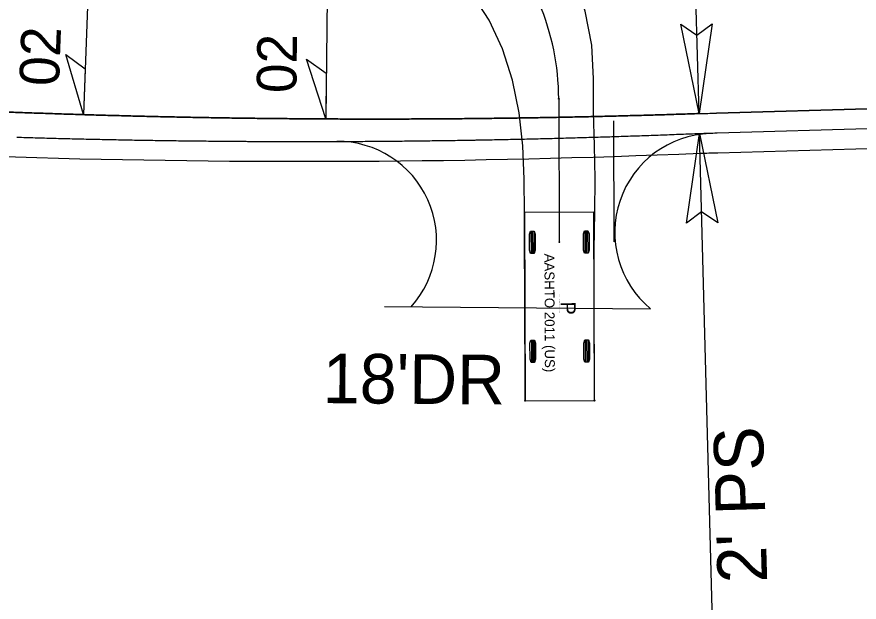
# Model space of a CAD drawing. Extents: x 1755545 to 1761252, y 736169 to 737766.
# Drawn here: x 1757215.5 to 1757300.5, y 736904.9 to 736964 of the extents above; entities that cross this region are included whole.
import ezdxf

# ---------------------------------------------------------------- set-up
doc = ezdxf.new("R2010")
doc.units = 0
for name, color, linetype in [('Exist Contamination Potential Cell', 7, 'Continuous'), ('Exist Cultural Church Label', 7, 'Continuous'), ('Old_Level_1', 7, 'Continuous'), ('Prop Dimension', 7, 'Continuous'), ('Prop Paved Shoulder', 7, 'Continuous'), ('Prop Shade Light', 7, 'Continuous'), ('Prop Superelevation Label', 7, 'Continuous'), ('Prop Terminator CELL', 7, 'Continuous'), ('Scratch_Level_2', 7, 'Continuous'), ('Scratch_Level_3', 7, 'Continuous'), ('Scratch_Level_4', 7, 'Continuous'), ('Scratch_Level_6', 7, 'Continuous')]:
    doc.layers.add(name, color=color, linetype=linetype)

msp = doc.modelspace()

# ---------------------------------------------------------------- linework, layer by layer
at = {"layer": 'Exist Contamination Potential Cell'}
msp.add_line((1757286.12, 736954.256), (1757374.712, 736956.772), dxfattribs=at)
msp.add_arc((1757258.672, 737920.867), 967, 271.521596, 271.626536, dxfattribs=at)
for points in [[(1757147.07, 736959.322), (1757147.994, 736959.222), (1757148.918, 736959.123), (1757149.843, 736959.024), (1757150.767, 736958.927), (1757151.691, 736958.831), (1757152.616, 736958.735), (1757153.54, 736958.64), (1757154.465, 736958.547), (1757155.39, 736958.454), (1757156.315, 736958.362), (1757157.24, 736958.271), (1757158.165, 736958.18), (1757159.09, 736958.091), (1757160.015, 736958.003), (1757160.94, 736957.915), (1757161.866, 736957.828), (1757162.791, 736957.743), (1757163.716, 736957.658), (1757164.642, 736957.574), (1757165.568, 736957.491), (1757166.493, 736957.408), (1757167.419, 736957.327), (1757168.345, 736957.247), (1757169.271, 736957.167), (1757170.197, 736957.088), (1757171.123, 736957.011), (1757172.049, 736956.934), (1757172.975, 736956.858), (1757173.901, 736956.783), (1757174.828, 736956.708), (1757175.754, 736956.635), (1757176.68, 736956.563), (1757177.607, 736956.491), (1757178.533, 736956.42), (1757179.46, 736956.351), (1757180.387, 736956.282), (1757181.314, 736956.214), (1757182.24, 736956.147), (1757183.167, 736956.08), (1757184.094, 736956.015), (1757185.021, 736955.951), (1757185.948, 736955.887), (1757186.875, 736955.824), (1757187.802, 736955.763), (1757188.73, 736955.702), (1757189.657, 736955.642), (1757190.584, 736955.583), (1757191.511, 736955.525), (1757192.439, 736955.467), (1757193.366, 736955.411), (1757194.294, 736955.355), (1757195.221, 736955.301), (1757196.149, 736955.247), (1757197.076, 736955.194), (1757198.004, 736955.142), (1757198.932, 736955.091), (1757199.86, 736955.041), (1757200.787, 736954.992), (1757201.715, 736954.943), (1757202.643, 736954.896), (1757203.571, 736954.849), (1757204.499, 736954.804), (1757205.427, 736954.759), (1757206.355, 736954.715), (1757207.283, 736954.672), (1757208.211, 736954.63), (1757209.139, 736954.588), (1757210.067, 736954.548), (1757210.995, 736954.508), (1757211.924, 736954.47), (1757212.852, 736954.432), (1757213.78, 736954.395), (1757214.708, 736954.359), (1757215.637, 736954.324)], [(1757215.637, 736954.324), (1757216.565, 736954.29), (1757217.494, 736954.257), (1757218.422, 736954.225), (1757219.35, 736954.193), (1757220.279, 736954.163), (1757221.207, 736954.133), (1757222.136, 736954.104), (1757223.064, 736954.076), (1757223.993, 736954.049), (1757224.921, 736954.023), (1757225.85, 736953.998), (1757226.779, 736953.974), (1757227.707, 736953.95), (1757228.636, 736953.928), (1757229.565, 736953.906), (1757230.493, 736953.885), (1757231.422, 736953.866), (1757232.351, 736953.847), (1757233.279, 736953.829), (1757234.208, 736953.811), (1757235.137, 736953.795), (1757236.065, 736953.78), (1757236.994, 736953.765), (1757237.923, 736953.752), (1757238.852, 736953.739), (1757239.78, 736953.727), (1757240.709, 736953.716), (1757241.638, 736953.706), (1757242.567, 736953.697), (1757243.495, 736953.689), (1757244.424, 736953.681), (1757245.353, 736953.675), (1757246.282, 736953.669), (1757247.21, 736953.664), (1757248.139, 736953.661), (1757249.068, 736953.658), (1757249.997, 736953.656), (1757250.925, 736953.655), (1757251.854, 736953.654), (1757252.783, 736953.655), (1757253.712, 736953.657), (1757254.64, 736953.659), (1757255.569, 736953.662), (1757256.498, 736953.667), (1757257.426, 736953.672), (1757258.355, 736953.678), (1757259.284, 736953.685), (1757260.212, 736953.692), (1757261.141, 736953.701), (1757262.07, 736953.711), (1757262.998, 736953.721), (1757263.927, 736953.732), (1757264.855, 736953.745), (1757265.784, 736953.758), (1757266.713, 736953.772), (1757267.641, 736953.787), (1757268.57, 736953.803), (1757269.498, 736953.819), (1757270.426, 736953.837), (1757271.355, 736953.855), (1757272.283, 736953.875), (1757273.212, 736953.895), (1757274.14, 736953.916), (1757275.068, 736953.938), (1757275.997, 736953.961), (1757276.925, 736953.985), (1757277.853, 736954.01), (1757278.781, 736954.035), (1757279.709, 736954.062), (1757280.638, 736954.089), (1757281.566, 736954.118), (1757282.494, 736954.147), (1757284.35, 736954.208)]]:
    msp.add_spline(points, degree=3, dxfattribs=at)
at = {"layer": 'Exist Cultural Church Label'}
for points in [[(1757222.253, 736954.101), (1757220.48, 736960.172), (1757222.427, 736958.722)], [(1757246.688, 736953.667), (1757244.762, 736959.691), (1757246.745, 736958.292)]]:
    msp.add_lwpolyline(points, close=True, dxfattribs=at)
at = {"layer": 'Old_Level_1'}
msp.add_line((1757252.603, 736934.737), (1757279.451, 736934.524), dxfattribs=at)
for centre, start, end in [((1757285.844, 736942.213), 92.13259, 230.2561), ((1757247.867, 736941.408), 317.995, 90.37061)]:
    msp.add_arc(centre, 10, start, end, dxfattribs=at)
at = {"layer": 'Prop Dimension'}
for p, q in [((1757284.35, 736954.208), (1757283.898, 736971.202)), ((1757286.368, 736878.235), (1757284.403, 736952.207))]:
    msp.add_line(p, q, dxfattribs=at)
at = {"layer": 'Prop Paved Shoulder'}
msp.add_line((1757286.177, 736952.257), (1757374.768, 736954.773), dxfattribs=at)
msp.add_arc((1757258.672, 737920.867), 969, 271.521596, 271.626536, dxfattribs=at)
msp.add_spline([(1757215.526, 736951.827), (1757216.457, 736951.799), (1757217.388, 736951.773), (1757218.319, 736951.747), (1757219.25, 736951.722), (1757220.181, 736951.698), (1757221.112, 736951.675), (1757222.043, 736951.653), (1757222.974, 736951.632), (1757223.905, 736951.612), (1757224.837, 736951.592), (1757225.768, 736951.574), (1757226.699, 736951.556), (1757227.63, 736951.539), (1757228.561, 736951.524), (1757229.492, 736951.509), (1757230.424, 736951.495), (1757231.355, 736951.481), (1757232.286, 736951.469), (1757233.217, 736951.458), (1757234.148, 736951.447), (1757235.079, 736951.438), (1757236.01, 736951.429), (1757236.942, 736951.421), (1757237.873, 736951.414), (1757238.804, 736951.408), (1757239.735, 736951.403), (1757240.666, 736951.399), (1757241.597, 736951.396), (1757242.528, 736951.393), (1757243.459, 736951.392), (1757244.39, 736951.391), (1757245.321, 736951.391), (1757246.253, 736951.392), (1757247.184, 736951.394), (1757248.115, 736951.397), (1757249.046, 736951.401), (1757249.977, 736951.406), (1757250.907, 736951.411), (1757251.838, 736951.418), (1757252.769, 736951.425), (1757253.7, 736951.434), (1757254.631, 736951.443), (1757255.562, 736951.453), (1757256.493, 736951.464), (1757257.424, 736951.476), (1757258.354, 736951.489), (1757259.285, 736951.502), (1757260.216, 736951.517), (1757261.147, 736951.532), (1757262.077, 736951.549), (1757263.008, 736951.566), (1757263.939, 736951.584), (1757264.869, 736951.603), (1757265.8, 736951.623), (1757266.73, 736951.644), (1757267.661, 736951.665), (1757268.591, 736951.688), (1757269.522, 736951.711), (1757270.452, 736951.736), (1757271.382, 736951.761), (1757272.313, 736951.787), (1757273.243, 736951.814), (1757274.173, 736951.842), (1757275.103, 736951.871), (1757276.033, 736951.901), (1757276.964, 736951.931), (1757277.894, 736951.963), (1757278.824, 736951.995), (1757279.754, 736952.029), (1757280.684, 736952.063), (1757281.613, 736952.098), (1757282.543, 736952.134), (1757284.403, 736952.209)], degree=3, dxfattribs=at)
at = {"layer": 'Prop Shade Light'}
for p, q in [((1757374.712, 736956.772), (1757286.12, 736954.256)), ((1757286.177, 736952.257), (1757374.768, 736954.773))]:
    msp.add_line(p, q, dxfattribs=at)
for radius in [967, 969]:
    msp.add_arc((1757258.672, 737920.867), radius, 271.521596, 271.626536, dxfattribs=at)
for points in [[(1757215.637, 736954.324), (1757214.708, 736954.359), (1757213.78, 736954.395), (1757212.852, 736954.432), (1757211.924, 736954.47), (1757210.995, 736954.508), (1757210.067, 736954.548), (1757209.139, 736954.588), (1757208.211, 736954.63), (1757207.283, 736954.672), (1757206.355, 736954.715), (1757205.427, 736954.759), (1757204.499, 736954.804), (1757203.571, 736954.849), (1757202.643, 736954.896), (1757201.715, 736954.943), (1757200.787, 736954.992), (1757199.86, 736955.041), (1757198.932, 736955.091), (1757198.004, 736955.142), (1757197.076, 736955.194), (1757196.149, 736955.247), (1757195.221, 736955.301), (1757194.294, 736955.355), (1757193.366, 736955.411), (1757192.744, 736955.449)], [(1757238.538, 736953.743), (1757237.923, 736953.752), (1757236.994, 736953.765), (1757236.065, 736953.78), (1757235.137, 736953.795), (1757234.208, 736953.811), (1757233.279, 736953.829), (1757232.351, 736953.847), (1757231.422, 736953.866), (1757230.493, 736953.885), (1757229.565, 736953.906), (1757228.636, 736953.928), (1757227.707, 736953.95), (1757226.779, 736953.974), (1757225.85, 736953.998), (1757224.921, 736954.023), (1757223.993, 736954.049), (1757223.064, 736954.076), (1757222.136, 736954.104), (1757221.207, 736954.133), (1757220.279, 736954.163), (1757219.35, 736954.193), (1757218.422, 736954.225), (1757217.494, 736954.257), (1757216.565, 736954.29), (1757215.637, 736954.324)], [(1757261.447, 736953.704), (1757261.141, 736953.701), (1757260.212, 736953.692), (1757259.284, 736953.685), (1757258.355, 736953.678), (1757257.426, 736953.672), (1757256.498, 736953.667), (1757255.569, 736953.662), (1757254.64, 736953.659), (1757253.712, 736953.657), (1757252.783, 736953.655), (1757251.854, 736953.654), (1757250.925, 736953.655), (1757249.997, 736953.656), (1757249.068, 736953.658), (1757248.139, 736953.661), (1757247.21, 736953.664), (1757246.282, 736953.669), (1757245.353, 736953.675), (1757244.424, 736953.681), (1757243.495, 736953.689), (1757242.567, 736953.697), (1757241.638, 736953.706), (1757240.709, 736953.716), (1757239.78, 736953.727), (1757238.852, 736953.739), (1757238.538, 736953.743)], [(1757284.35, 736954.208), (1757282.494, 736954.147), (1757281.566, 736954.118), (1757280.638, 736954.089), (1757279.709, 736954.062), (1757278.781, 736954.035), (1757277.853, 736954.01), (1757276.925, 736953.985), (1757275.997, 736953.961), (1757275.068, 736953.938), (1757274.14, 736953.916), (1757273.212, 736953.895), (1757272.283, 736953.875), (1757271.355, 736953.855), (1757270.426, 736953.837), (1757269.498, 736953.819), (1757268.57, 736953.803), (1757267.641, 736953.787), (1757266.713, 736953.772), (1757265.784, 736953.758), (1757264.855, 736953.745), (1757263.927, 736953.732), (1757262.998, 736953.721), (1757262.07, 736953.711), (1757261.447, 736953.704)], [(1757261.449, 736951.537), (1757262.077, 736951.549), (1757263.008, 736951.566), (1757263.939, 736951.584), (1757264.869, 736951.603), (1757265.8, 736951.623), (1757266.73, 736951.644), (1757267.661, 736951.665), (1757268.591, 736951.688), (1757269.522, 736951.711), (1757270.452, 736951.736), (1757271.382, 736951.761), (1757272.313, 736951.787), (1757273.243, 736951.814), (1757274.173, 736951.842), (1757275.103, 736951.871), (1757276.033, 736951.901), (1757276.964, 736951.931), (1757277.894, 736951.963), (1757278.824, 736951.995), (1757279.754, 736952.029), (1757280.684, 736952.063), (1757281.613, 736952.098), (1757282.543, 736952.134), (1757284.403, 736952.209)], [(1757215.526, 736951.827), (1757216.457, 736951.799), (1757217.388, 736951.773), (1757218.319, 736951.747), (1757219.25, 736951.722), (1757220.181, 736951.698), (1757221.112, 736951.675), (1757222.043, 736951.653), (1757222.974, 736951.632), (1757223.905, 736951.612), (1757224.837, 736951.592), (1757225.768, 736951.574), (1757226.699, 736951.556), (1757227.63, 736951.539), (1757228.561, 736951.524), (1757229.492, 736951.509), (1757230.424, 736951.495), (1757231.355, 736951.481), (1757232.286, 736951.469), (1757233.217, 736951.458), (1757234.148, 736951.447), (1757235.079, 736951.438), (1757236.01, 736951.429), (1757236.942, 736951.421), (1757237.873, 736951.414), (1757238.486, 736951.41)], [(1757238.486, 736951.41), (1757238.804, 736951.408), (1757239.735, 736951.403), (1757240.666, 736951.399), (1757241.597, 736951.396), (1757242.528, 736951.393), (1757243.459, 736951.392), (1757244.39, 736951.391), (1757245.321, 736951.391), (1757246.253, 736951.392), (1757247.184, 736951.394), (1757248.115, 736951.397), (1757249.046, 736951.401), (1757249.977, 736951.406), (1757250.907, 736951.411), (1757251.838, 736951.418), (1757252.769, 736951.425), (1757253.7, 736951.434), (1757254.631, 736951.443), (1757255.562, 736951.453), (1757256.493, 736951.464), (1757257.424, 736951.476), (1757258.354, 736951.489), (1757259.285, 736951.502), (1757260.216, 736951.517), (1757261.147, 736951.532), (1757261.449, 736951.537)]]:
    msp.add_spline(points, degree=3, dxfattribs=at)
at = {"layer": 'Prop Superelevation Label'}
for p, q in [((1757223.465, 736986.271), (1757222.253, 736954.101)), ((1757247.095, 736986.568), (1757246.688, 736953.667))]:
    msp.add_line(p, q, dxfattribs=at)
at = {"layer": 'Prop Terminator CELL'}
for points in [[(1757285.66, 736963.246), (1757284.35, 736954.208), (1757282.51, 736963.212), (1757284.14, 736962.105)], [(1757283.092, 736943.169), (1757284.403, 736952.207), (1757286.243, 736943.203), (1757284.613, 736944.31)]]:
    msp.add_lwpolyline(points, close=True, dxfattribs=at)
at = {"layer": 'Scratch_Level_2'}
for p, q in [((1757270.198, 736955.7), (1757270.254, 736941.247)), ((1757275.707, 736953.469), (1757275.754, 736941.269)), ((1757273.742, 736944.261), (1757266.743, 736944.234)), ((1757266.743, 736944.234), (1757266.816, 736925.234)), ((1757266.743, 736944.234), (1757266.743, 736944.234)), ((1757273.816, 736925.261), (1757273.742, 736944.261)), ((1757267.39, 736942.361), (1757267.399, 736940.111)), ((1757267.531, 736942.362), (1757267.54, 736940.112)), ((1757267.672, 736942.362), (1757267.68, 736940.112)), ((1757272.828, 736942.382), (1757272.837, 736940.132)), ((1757272.969, 736942.383), (1757272.977, 736940.133)), ((1757273.109, 736942.383), (1757273.118, 736940.133)), ((1757267.433, 736931.361), (1757267.442, 736929.111)), ((1757267.574, 736931.362), (1757267.583, 736929.112)), ((1757267.714, 736931.362), (1757267.723, 736929.112)), ((1757272.871, 736931.382), (1757272.879, 736929.132)), ((1757273.011, 736931.383), (1757273.02, 736929.133)), ((1757273.152, 736931.383), (1757273.161, 736929.133)), ((1757266.816, 736925.234), (1757273.816, 736925.261))]:
    msp.add_line(p, q, dxfattribs=at)
for points in [[(1757273.816, 736925.261), (1757273.802, 736929.061), (1757273.787, 736932.861), (1757273.772, 736936.661), (1757273.761, 736940.461), (1757273.838, 736944.263), (1757273.838, 736944.263), (1757273.838, 736944.263), (1757273.873, 736947.632), (1757273.815, 736950.998), (1757273.703, 736954.344), (1757273.69, 736957.706), (1757273.539, 736961.091), (1757272.863, 736964.536), (1757271.664, 736967.948), (1757270.158, 736970.915)], [(1757266.816, 736925.234), (1757266.802, 736929.034), (1757266.787, 736932.834), (1757266.772, 736936.634), (1757266.757, 736940.434), (1757266.743, 736944.234), (1757266.743, 736944.234), (1757266.713, 736947.595), (1757266.57, 736950.952), (1757266.207, 736954.292), (1757265.541, 736957.583), (1757264.524, 736960.739), (1757263.179, 736963.618), (1757261.539, 736966.185), (1757259.841, 736968.215)]]:
    msp.add_lwpolyline(points, dxfattribs=at)
for points in [[(1757267.356, 736942.361), (1757267.707, 736942.362), (1757267.814, 736942.048), (1757267.82, 736940.428), (1757267.715, 736940.112), (1757267.364, 736940.111), (1757267.257, 736940.426), (1757267.251, 736942.046)], [(1757272.793, 736942.382), (1757273.144, 736942.383), (1757273.251, 736942.069), (1757273.257, 736940.449), (1757273.153, 736940.133), (1757272.802, 736940.132), (1757272.695, 736940.447), (1757272.689, 736942.067)], [(1757267.398, 736931.361), (1757267.749, 736931.362), (1757267.856, 736931.048), (1757267.863, 736929.428), (1757267.758, 736929.112), (1757267.407, 736929.111), (1757267.3, 736929.426), (1757267.294, 736931.046)], [(1757272.836, 736931.382), (1757273.187, 736931.384), (1757273.294, 736931.069), (1757273.3, 736929.449), (1757273.195, 736929.134), (1757272.844, 736929.132), (1757272.738, 736929.447), (1757272.731, 736931.067)]]:
    msp.add_lwpolyline(points, close=True, dxfattribs=at)
for centre in [(1757270.198, 736955.7), (1757270.254, 736941.247), (1757266.816, 736925.234), (1757273.816, 736925.261)]:
    msp.add_circle(centre, 0.0417, dxfattribs=at)
msp.add_arc((1757245.198, 736955.603), 25, 0.22255, 90.97942, dxfattribs=at)
at = {"layer": 'Scratch_Level_3'}
msp.add_arc((1757251.634, 737921.129), 967.474, 263.795377, 271.937839, dxfattribs=at)
at = {"layer": 'Scratch_Level_6'}
msp.add_line((1757286.234, 736950.258), (1757374.825, 736952.774), dxfattribs=at)
for centre, radius, start, end in [((1757244.599, 737921.442), 972.05, 264.207509, 272.349971), ((1757258.672, 737920.867), 971, 271.521596, 271.626536)]:
    msp.add_arc(centre, radius, start, end, dxfattribs=at)

# ---------------------------------------------------------------- texts
at = {"layer": 'Prop Dimension'}
msp.add_text("2' PS", height=5, rotation=91.62654, dxfattribs=at).set_placement((1757291.235, 736906.934))
at = {"layer": 'Prop Superelevation Label'}
for rotation, p in [(87.8426, (1757219.767, 736956.935)), (89.29008, (1757243.723, 736956.258))]:
    msp.add_text('02', height=4, rotation=rotation, dxfattribs=at).set_placement(p)
at = {"layer": 'Scratch_Level_2'}
for s, height, p in [('AASHTO 2011 (US)', 1, (1757268.754, 736940.081)), ('(c) 2014 Transoft Solutions, Inc. All rights reserved.', 0.06, (1757270.245, 736935.97)), ('P', 1.5, (1757270.397, 736935.248))]:
    msp.add_text(s, height=height, rotation=270.22255, dxfattribs=at).set_placement(p)
at = {"layer": 'Scratch_Level_4'}
msp.add_text("18'DR", height=5, rotation=359.54477, dxfattribs=at).set_placement((1757246.382, 736925.011))

doc.saveas('drawing.dxf')
